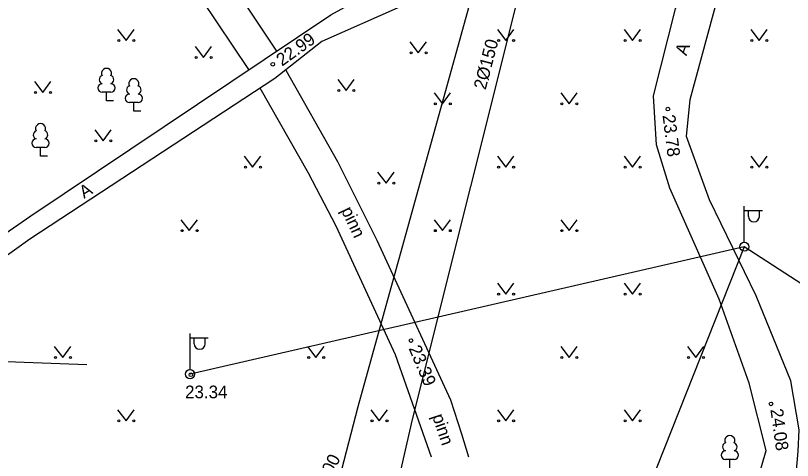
# Model space of a CAD drawing. Extents: x 714391 to 714584, y 6589993 to 6590151.
# Drawn here: x 714490.89 to 714533.84, y 6590014.81 to 6590039.38 of the extents above; entities that cross this region are included whole.
import ezdxf

# ---------------------------------------------------------------- set-up
doc = ezdxf.new("R2010")
doc.units = 0
for name, color, linetype in [('HALJASTUS', 7, 'Continuous'), ('KORGUS', 7, 'Continuous'), ('MPKAABEL', 7, 'Continuous'), ('POST', 7, 'Continuous'), ('PUU', 7, 'Continuous'), ('SITRASS', 7, 'Continuous'), ('SKTRASS', 7, 'Continuous'), ('TEE', 7, 'Continuous'), ('TTRASS', 7, 'Continuous')]:
    doc.layers.add(name, color=color, linetype=linetype)

msp = doc.modelspace()

# ---------------------------------------------------------------- linework, layer by layer
at = {"layer": 'HALJASTUS'}
for p, q in [((714496.537, 6590038.607), (714497, 6590038)), ((714497, 6590038), (714497.446, 6590038.607)), ((714517.537, 6590038.607), (714518, 6590038)), ((714518, 6590038), (714518.446, 6590038.607)), ((714524.537, 6590038.607), (714525, 6590038)), ((714525, 6590038), (714525.446, 6590038.607)), ((714531.537, 6590038.607), (714532, 6590038)), ((714532, 6590038), (714532.446, 6590038.607)), ((714500.818, 6590037.663), (714501.281, 6590037.056)), ((714501.281, 6590037.056), (714501.727, 6590037.663)), ((714512.696, 6590037.928), (714513.159, 6590037.321)), ((714513.159, 6590037.321), (714513.605, 6590037.928)), ((714491.938, 6590035.733), (714492.401, 6590035.126)), ((714492.401, 6590035.126), (714492.847, 6590035.733)), ((714508.708, 6590035.845), (714509.171, 6590035.238)), ((714509.171, 6590035.238), (714509.617, 6590035.845)), ((714514.037, 6590035.107), (714514.5, 6590034.5)), ((714514.5, 6590034.5), (714514.946, 6590035.107)), ((714521.037, 6590035.107), (714521.5, 6590034.5)), ((714521.5, 6590034.5), (714521.946, 6590035.107)), ((714495.276, 6590033.063), (714495.739, 6590032.456)), ((714495.739, 6590032.456), (714496.185, 6590033.063)), ((714503.537, 6590031.607), (714504, 6590031)), ((714504, 6590031), (714504.446, 6590031.607)), ((714517.537, 6590031.607), (714518, 6590031)), ((714518, 6590031), (714518.446, 6590031.607)), ((714524.537, 6590031.607), (714525, 6590031)), ((714525, 6590031), (714525.446, 6590031.607)), ((714531.537, 6590031.607), (714532, 6590031)), ((714532, 6590031), (714532.446, 6590031.607)), ((714510.91, 6590030.728), (714511.373, 6590030.121)), ((714511.373, 6590030.121), (714511.819, 6590030.728)), ((714500.037, 6590028.107), (714500.5, 6590027.5)), ((714500.5, 6590027.5), (714500.946, 6590028.107)), ((714514.037, 6590028.107), (714514.5, 6590027.5)), ((714514.5, 6590027.5), (714514.946, 6590028.107)), ((714521.037, 6590028.107), (714521.5, 6590027.5)), ((714521.5, 6590027.5), (714521.946, 6590028.107)), ((714517.537, 6590024.607), (714518, 6590024)), ((714518, 6590024), (714518.446, 6590024.607)), ((714524.537, 6590024.607), (714525, 6590024)), ((714525, 6590024), (714525.446, 6590024.607)), ((714493.037, 6590021.107), (714493.5, 6590020.5)), ((714493.5, 6590020.5), (714493.946, 6590021.107)), ((714507.037, 6590021.107), (714507.5, 6590020.5)), ((714507.5, 6590020.5), (714507.946, 6590021.107)), ((714521.037, 6590021.107), (714521.5, 6590020.5)), ((714521.5, 6590020.5), (714521.946, 6590021.107)), ((714528.037, 6590021.107), (714528.5, 6590020.5)), ((714528.5, 6590020.5), (714528.946, 6590021.107)), ((714496.537, 6590017.607), (714497, 6590017)), ((714497, 6590017), (714497.446, 6590017.607)), ((714510.537, 6590017.607), (714511, 6590017)), ((714511, 6590017), (714511.446, 6590017.607)), ((714517.537, 6590017.607), (714518, 6590017)), ((714518, 6590017), (714518.446, 6590017.607)), ((714524.537, 6590017.607), (714525, 6590017)), ((714525, 6590017), (714525.446, 6590017.607))]:
    msp.add_line(p, q, dxfattribs=at)
for centre in [(714496.599, 6590038), (714497.428, 6590038), (714517.599, 6590038), (714518.428, 6590038), (714524.599, 6590038), (714525.428, 6590038), (714531.599, 6590038), (714532.428, 6590038), (714512.758, 6590037.321), (714513.587, 6590037.321), (714500.88, 6590037.056), (714501.709, 6590037.056), (714492, 6590035.126), (714492.829, 6590035.126), (714508.77, 6590035.238), (714509.599, 6590035.238), (714514.099, 6590034.5), (714514.928, 6590034.5), (714521.099, 6590034.5), (714521.928, 6590034.5), (714495.338, 6590032.456), (714496.167, 6590032.456), (714503.599, 6590031), (714504.428, 6590031), (714517.599, 6590031), (714518.428, 6590031), (714524.599, 6590031), (714525.428, 6590031), (714531.599, 6590031), (714532.428, 6590031), (714510.972, 6590030.121), (714511.801, 6590030.121), (714500.099, 6590027.5), (714500.928, 6590027.5), (714514.099, 6590027.5), (714514.928, 6590027.5), (714521.099, 6590027.5), (714521.928, 6590027.5), (714517.599, 6590024), (714518.428, 6590024), (714524.599, 6590024), (714525.428, 6590024), (714493.099, 6590020.5), (714493.928, 6590020.5), (714507.099, 6590020.5), (714507.928, 6590020.5), (714521.099, 6590020.5), (714521.928, 6590020.5), (714528.099, 6590020.5), (714528.928, 6590020.5), (714496.599, 6590017), (714497.428, 6590017), (714510.599, 6590017), (714511.428, 6590017), (714517.599, 6590017), (714518.428, 6590017), (714524.599, 6590017), (714525.428, 6590017)]:
    msp.add_circle(centre, 0.055, dxfattribs=at)
at = {"layer": 'KORGUS'}
for centre in [(714505.112, 6590036.69), (714526.955, 6590034.212), (714512.756, 6590021.433), (714500.587, 6590019.546), (714532.656, 6590017.934)]:
    msp.add_circle(centre, 0.1, dxfattribs=at)
at = {"layer": 'MPKAABEL'}
for points in [[(714565.296, 6590047.518), (714562.179, 6590038.578), (714559.533, 6590030.225), (714556.889, 6590017.808), (714556.781, 6590017.088), (714556.359, 6590014.294), (714555.801, 6590010.589), (714547.733, 6590015.896), (714531.176, 6590026.61), (714500.538, 6590019.577)], [(714531.176, 6590026.61), (714525.138, 6590011.422), (714523.319, 6590006.504), (714517.694, 6589992.711)]]:
    msp.add_lwpolyline(points, dxfattribs=at)
at = {"layer": 'POST'}
for p, q in [((714531.176, 6590026.86), (714531.176, 6590028.86)), ((714531.176, 6590028.61), (714532.176, 6590028.61)), ((714531.403, 6590028.289), (714531.403, 6590028.61)), ((714532.015, 6590028.289), (714532.015, 6590028.61)), ((714500.538, 6590019.827), (714500.538, 6590021.827)), ((714500.538, 6590021.577), (714501.538, 6590021.577)), ((714500.765, 6590021.256), (714500.765, 6590021.577)), ((714501.377, 6590021.256), (714501.377, 6590021.577))]:
    msp.add_line(p, q, dxfattribs=at)
for centre in [(714531.176, 6590026.61), (714500.538, 6590019.577)]:
    msp.add_circle(centre, 0.25, dxfattribs=at)
for centre in [(714531.709, 6590028.289), (714501.071, 6590021.256)]:
    msp.add_arc(centre, 0.306, 180, 0, dxfattribs=at)
at = {"layer": 'PUU'}
for p, q in [((714496.163, 6590035.14), (714495.683, 6590035.14)), ((714495.923, 6590034.665), (714495.923, 6590035.14)), ((714496.303, 6590034.665), (714495.923, 6590034.665)), ((714497.672, 6590034.568), (714497.192, 6590034.568)), ((714497.432, 6590034.093), (714497.432, 6590034.568)), ((714497.812, 6590034.093), (714497.432, 6590034.093)), ((714492.516, 6590032.088), (714492.036, 6590032.088)), ((714492.276, 6590031.613), (714492.276, 6590032.088)), ((714492.656, 6590031.613), (714492.276, 6590031.613)), ((714530.617, 6590014.866), (714530.137, 6590014.866)), ((714530.377, 6590014.391), (714530.377, 6590014.866))]:
    msp.add_line(p, q, dxfattribs=at)
for centre, radius, start, end in [((714495.923, 6590036.185), 0.277, 332.5799, 207.4201), ((714495.753, 6590035.838), 0.233, 109.0217, 253.1415), ((714496.093, 6590035.838), 0.233, 286.8508, 70.9859), ((714495.686, 6590035.377), 0.238, 90.0016, 269.3953), ((714496.16, 6590035.377), 0.238, 270.6047, 89.9984), ((714497.262, 6590035.266), 0.233, 109.0217, 253.1415), ((714497.432, 6590035.613), 0.277, 332.5799, 207.4201), ((714497.602, 6590035.266), 0.233, 286.8508, 70.9859), ((714497.195, 6590034.805), 0.238, 90.0016, 269.3953), ((714497.669, 6590034.805), 0.238, 270.6047, 89.9984), ((714492.276, 6590033.133), 0.277, 332.5799, 207.4201), ((714492.106, 6590032.786), 0.233, 109.0217, 253.1415), ((714492.446, 6590032.786), 0.233, 286.8508, 70.9859), ((714492.039, 6590032.325), 0.238, 90.0016, 269.3953), ((714492.513, 6590032.325), 0.238, 270.6047, 89.9984), ((714530.377, 6590015.911), 0.277, 332.5799, 207.4201), ((714530.207, 6590015.564), 0.233, 109.0217, 253.1415), ((714530.547, 6590015.564), 0.233, 286.8508, 70.9859), ((714530.14, 6590015.103), 0.238, 90.0016, 269.3953), ((714530.614, 6590015.103), 0.238, 270.6047, 89.9984)]:
    msp.add_arc(centre, radius, start, end, dxfattribs=at)
at = {"layer": 'SITRASS'}
msp.add_line((714469.869, 6590021.038), (714494.838, 6590020.104), dxfattribs=at)
at = {"layer": 'SKTRASS'}
msp.add_lwpolyline([(714531.495, 6590096.001), (714522.972, 6590065.168), (714519.718, 6590053.426), (714509.807, 6590017.772), (714505.951, 6590002.864)], dxfattribs=at)
at = {"layer": 'TEE'}
for points in [[(714503.783, 6590036.391), (714498.601, 6590044.145), (714494.073, 6590051.394), (714489.657, 6590058.462), (714484.091, 6590067.913), (714485.295, 6590068.584), (714495.449, 6590052.222), (714495.743, 6590051.781), (714495.449, 6590052.222), (714505.314, 6590037.415)], [(714470.452, 6590014.088), (714483.473, 6590022.62), (714491.732, 6590028.328), (714508.314, 6590039.422), (714510.811, 6590040.796), (714513.08, 6590041.27), (714515.342, 6590041.216), (714516.939, 6590047.426), (714520.722, 6590062.481)], [(714525.477, 6590005.373), (714525.684, 6590006.074), (714527.69, 6590005.573), (714531.538, 6590012.432), (714532.385, 6590015.369), (714531.445, 6590019.084), (714529.795, 6590023.709), (714527.067, 6590029.841), (714526.32, 6590032.242), (714526.158, 6590034.948), (714527.384, 6590039.748), (714530.089, 6590049.424), (714531.112, 6590053.289), (714520.888, 6590055.232), (714516.962, 6590040.074), (714512.15, 6590039.854), (714507.831, 6590037.94), (714505.233, 6590035.896), (714491.681, 6590027.029), (714484.169, 6590021.661), (714470.258, 6590012.413)], [(714530.594, 6590004.671), (714529.575, 6590005.355), (714533.957, 6590012.977), (714534.157, 6590015.322), (714534.216, 6590016.497), (714533.749, 6590019.201), (714531.843, 6590023.902), (714529.246, 6590029.211), (714527.989, 6590032.696), (714528.19, 6590034.745), (714530.462, 6590043.175), (714532.838, 6590052.177), (714538.719, 6590050.416), (714545.918, 6590048.286), (714551.944, 6590046.002), (714557.184, 6590043.351), (714560.131, 6590041.46), (714562.296, 6590039.644), (714565.486, 6590037.034), (714564.832, 6590036.22), (714560.292, 6590037.889), (714555.09, 6590040.381)], [(714505.835, 6590036.37), (714508.691, 6590031.313), (714510.872, 6590026.981), (714514.938, 6590018.164), (714515.554, 6590016.285), (714515.924, 6590015.017)], [(714513.89, 6590014.993), (714511.904, 6590020.637), (714508.626, 6590027.75), (714507.089, 6590030.667), (714504.423, 6590035.366)]]:
    msp.add_lwpolyline(points, dxfattribs=at)
at = {"layer": 'TTRASS'}
msp.add_lwpolyline([(714510.928, 6590008.703), (714512.829, 6590017.079), (714522.511, 6590055.684), (714522.522, 6590055.681), (714534.537, 6590104.393)], dxfattribs=at)

# ---------------------------------------------------------------- texts
at = {"layer": 'KORGUS'}
for s, rotation, p in [('22.99', 35.5124, (714505.622, 6590036.553)), ('23.78', 277.0769, (714526.657, 6590033.868)), ('23.39', 292.9682, (714512.613, 6590021)), ('24.08', 278.1005, (714532.617, 6590017.63))]:
    msp.add_text(s, height=0.7, rotation=rotation, dxfattribs=at).set_placement(p)
msp.add_text('23.34', height=0.7, dxfattribs=at).set_placement((714500.265, 6590018.247))
at = {"layer": 'SKTRASS'}
msp.add_text('%%c100', height=0.7, rotation=63.1575, dxfattribs=at).set_placement((714507.843, 6590012.885))
at = {"layer": 'TEE'}
for s, rotation, p in [('A', 69.7195, (714527.978, 6590037.124)), ('A', 31.2657, (714494.679, 6590029.255)), ('pinn', 295.4025, (714508.872, 6590028.63)), ('pinn', 288.6934, (714513.914, 6590017.262))]:
    msp.add_text(s, height=0.7, rotation=rotation, dxfattribs=at).set_placement(p)
at = {"layer": 'TTRASS'}
msp.add_text('2%%c150', height=0.7, rotation=75.2973, dxfattribs=at).set_placement((714516.878, 6590035.245))

doc.saveas('drawing.dxf')
